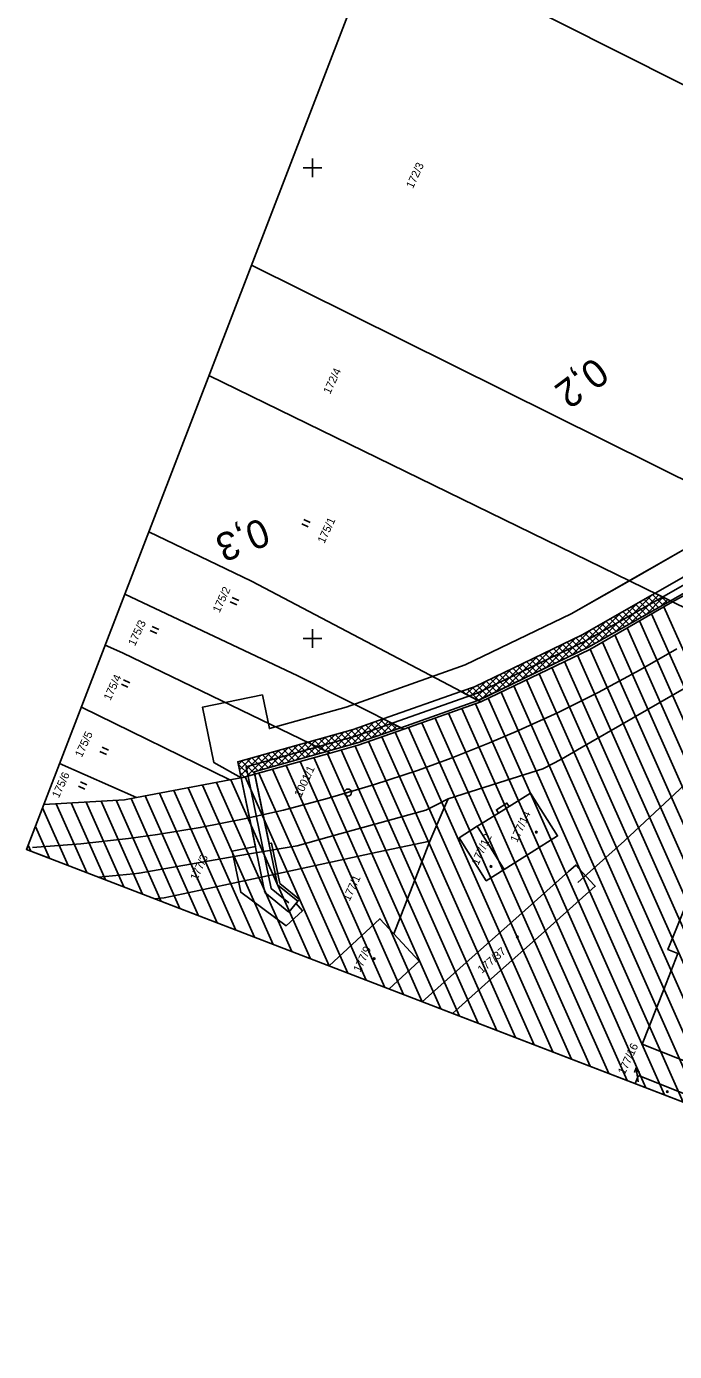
# Model space of a CAD drawing. Extents: x -755061 to -754557, y -1162352 to -1161657.
# Drawn here: x -755060.7 to -754923.1, y -1162351.5 to -1162070 of the extents above; entities that cross this region are included whole.
import ezdxf

# ---------------------------------------------------------------- set-up
doc = ezdxf.new("R2010")
doc.units = 0
for name, color, linetype in [('ADJ_Formát', 7, 'Continuous'), ('ADJ_Síť', 7, 'Continuous'), ('DTA-TZ', 7, 'Continuous'), ('DTA_DZ_DO_hranice', 7, 'Continuous'), ('DTA_DZ_DO_ostatní', 7, 'Continuous'), ('DTA_DZ_DO_ZPF', 7, 'Continuous'), ('DTA_ochranné pásmo', 7, 'Continuous'), ('DTA_projektovaný_stav', 7, 'Continuous'), ('DTA_správa_investora', 7, 'Continuous'), ('DTA_VB', 7, 'Continuous'), ('KN_Vrstva 55', 7, 'Continuous'), ('KN_Vrstva 56', 7, 'Continuous'), ('KN_Vrstva 57', 7, 'Continuous'), ('KN_Vrstva 58', 7, 'Continuous'), ('KN_Vrstva 59', 7, 'Continuous'), ('Staniceni a namezniky', 7, 'Continuous'), ('Vrstva 1', 7, 'Continuous'), ('Vrstva 53', 7, 'Continuous')]:
    doc.layers.add(name, color=color, linetype=linetype)

msp = doc.modelspace()

# ---------------------------------------------------------------- linework, layer by layer
at = {"layer": 'ADJ_Formát'}
msp.add_line((-755060.75, -1162244.84), (-755056.08, -1162246.64), dxfattribs=at)
msp.add_lwpolyline([(-754909.9, -1161852.87), (-754632.71, -1161959.54), (-754783.57, -1162351.52), (-755060.75, -1162244.84)], close=True, dxfattribs=at)
at = {"layer": 'ADJ_Síť'}
for points in [[(-755000, -1162098), (-755000, -1162100), (-755000, -1162102)], [(-754998, -1162100), (-755000, -1162100), (-755002, -1162100)], [(-754998, -1162200), (-755000, -1162200), (-755002, -1162200)], [(-754998, -1162200), (-755000, -1162200), (-755002, -1162200)], [(-755000, -1162198), (-755000, -1162200), (-755000, -1162202)], [(-755000, -1162198), (-755000, -1162200), (-755000, -1162202)]]:
    msp.add_lwpolyline(points, dxfattribs=at)
at = {"layer": 'DTA-TZ'}
msp.add_lwpolyline([(-754923.5, -1162192.2), (-754927.24, -1162190.37), (-754917.66, -1162184.92), (-754903.67, -1162174.98), (-754894.6, -1162165.92), (-754868.47, -1162140.62), (-754868.42, -1162135.23), (-754861.18, -1162138.93), (-754862.16, -1162142.69), (-754868.56, -1162149.23), (-754896.07, -1162173.88), (-754915.78, -1162187.87), (-754923.5, -1162192.2)], dxfattribs=at)
msp.add_lwpolyline([(-754984.97, -1162217.1), (-754968.47, -1162211.27), (-754964.26, -1162213.49), (-754980.63, -1162219.28)], close=True, dxfattribs=at)
at = {"layer": 'DTA_DZ_DO_hranice'}
for points in [[(-754920.36, -1162180.69), (-754945.08, -1162194.78), (-754967.54, -1162205.63), (-754992.85, -1162214.58), (-755009.16, -1162219.14), (-755010.64, -1162212), (-755023.37, -1162214.63), (-755020.94, -1162226.38), (-755020.94, -1162226.38), (-755020.94, -1162226.38), (-755015.16, -1162229.61), (-755012.14, -1162244.2), (-755017.04, -1162245.22), (-755015.23, -1162253.93), (-755005.62, -1162261.05), (-755002.11, -1162257.86), (-755003.57, -1162256.25), (-755002.73, -1162255.48), (-755006.94, -1162252.04), (-755008.71, -1162243.49), (-755009.2, -1162243.6), (-755012.26, -1162228.83)], [(-755012.26, -1162228.83), (-754996.22, -1162224.35), (-754990.29, -1162222.69), (-754980.63, -1162219.28), (-754964.26, -1162213.49), (-754941.12, -1162202.31), (-754923.5, -1162192.2), (-754915.78, -1162187.87)]]:
    msp.add_lwpolyline(points, dxfattribs=at)
at = {"layer": 'DTA_DZ_DO_ostatní'}
msp.add_lwpolyline([(-755015.16, -1162229.61), (-755012.14, -1162244.2), (-755017.04, -1162245.22), (-755015.23, -1162253.93), (-755005.62, -1162261.05), (-755002.11, -1162257.86), (-755003.57, -1162256.25), (-755002.73, -1162255.48), (-755006.94, -1162252.04), (-755008.71, -1162243.49), (-755009.2, -1162243.6), (-755012.26, -1162228.83), (-755014.83, -1162229.55)], close=True, dxfattribs=at)
at = {"layer": 'DTA_DZ_DO_ZPF'}
msp.add_lwpolyline([(-754920.36, -1162180.69), (-754932.68, -1162187.72), (-754945.08, -1162194.78), (-754967.54, -1162205.63), (-754992.85, -1162214.58), (-755009.16, -1162219.14), (-755010.64, -1162212), (-755023.37, -1162214.63), (-755020.94, -1162226.38), (-755015.16, -1162229.61), (-755014.83, -1162229.55), (-755012.26, -1162228.83), (-754996.22, -1162224.35), (-754990.29, -1162222.69), (-754980.63, -1162219.28), (-754984.97, -1162217.1), (-754968.47, -1162211.27), (-754964.26, -1162213.49), (-754941.12, -1162202.31), (-754923.5, -1162192.2), (-754927.24, -1162190.37), (-754917.66, -1162184.92)], dxfattribs=at)
at = {"layer": 'DTA_ochranné pásmo'}
for p, q in [((-754917.66, -1162184.92), (-754927.24, -1162190.37)), ((-754923.98, -1162191.97), (-754916.05, -1162187.45)), ((-754942.75, -1162199.21), (-754927.24, -1162190.37)), ((-754927.24, -1162190.37), (-754923.98, -1162191.97)), ((-754923.98, -1162191.97), (-754941.35, -1162201.87)), ((-754965.61, -1162210.25), (-754942.75, -1162199.21)), ((-754941.35, -1162201.87), (-754964.45, -1162213.03)), ((-754984.97, -1162217.1), (-754968.47, -1162211.27)), ((-754968.47, -1162211.27), (-754965.61, -1162210.25)), ((-754964.86, -1162213.17), (-754968.47, -1162211.27)), ((-754981.25, -1162218.97), (-754964.86, -1162213.17)), ((-754964.45, -1162213.03), (-754964.86, -1162213.17)), ((-755015.87, -1162226.21), (-754991.35, -1162219.35)), ((-754991.35, -1162219.35), (-754984.97, -1162217.1)), ((-754981.25, -1162218.97), (-754990.44, -1162222.21)), ((-754984.97, -1162217.1), (-754981.25, -1162218.97)), ((-754990.44, -1162222.21), (-755012.36, -1162228.34)), ((-755010.12, -1162253.96), (-755015.87, -1162226.21)), ((-755014.83, -1162229.55), (-755015.16, -1162229.61)), ((-755012.26, -1162228.83), (-755014.83, -1162229.55)), ((-755012.36, -1162228.34), (-755007.4, -1162252.32)), ((-755007.4, -1162252.32), (-755003.11, -1162255.82)), ((-755005, -1162258.15), (-755010.12, -1162253.96)), ((-755003.11, -1162255.82), (-755005, -1162258.15))]:
    msp.add_line(p, q, dxfattribs=at)
at = {"layer": 'DTA_projektovaný_stav'}
msp.add_lwpolyline([(-754758.34, -1161933.06), (-754762.34, -1161937.68), (-754763.29, -1161936.85), (-754776.47, -1161949.62), (-754777.37, -1161978.41), (-754796.3, -1162026.28), (-754809.87, -1162057.58), (-754831.07, -1162091.65), (-754857.54, -1162133.93), (-754885.68, -1162161.18), (-754896.77, -1162171.93), (-754916.86, -1162186.18), (-754942.05, -1162200.54), (-754965.03, -1162211.64), (-754990.89, -1162220.78), (-755014.11, -1162227.27), (-755008.76, -1162253.14), (-755005.05, -1162256.17)], dxfattribs=at)
at = {"layer": 'DTA_správa_investora'}
for p, q in [((-754878.81, -1162298.02), (-754925.34, -1162193.26)), ((-754881.97, -1162305.67), (-754930.57, -1162196.26)), ((-754880.39, -1162301.85), (-754927.96, -1162194.76)), ((-754885.62, -1162312.24), (-754935.81, -1162199.26)), ((-754883.56, -1162309.49), (-754933.19, -1162197.76)), ((-754893.54, -1162309.19), (-754941.04, -1162202.26)), ((-754889.58, -1162310.72), (-754938.42, -1162200.76)), ((-754901.46, -1162306.15), (-754946.44, -1162204.88)), ((-754897.5, -1162307.67), (-754943.74, -1162203.57)), ((-754909.38, -1162303.1), (-754951.85, -1162207.49)), ((-754905.42, -1162304.62), (-754949.14, -1162206.19)), ((-754917.3, -1162300.05), (-754957.25, -1162210.1)), ((-754913.34, -1162301.58), (-754954.55, -1162208.8)), ((-754929.17, -1162295.48), (-754965.41, -1162213.9)), ((-754925.22, -1162297), (-754962.66, -1162212.72)), ((-754921.26, -1162298.53), (-754959.95, -1162211.41)), ((-754941.05, -1162290.91), (-754973.92, -1162216.91)), ((-754937.09, -1162292.43), (-754971.09, -1162215.9)), ((-754933.13, -1162293.96), (-754968.25, -1162214.9)), ((-754948.97, -1162287.86), (-754979.6, -1162218.91)), ((-754945.01, -1162289.38), (-754976.76, -1162217.91)), ((-754960.85, -1162283.29), (-754988.11, -1162221.92)), ((-754956.89, -1162284.81), (-754985.27, -1162220.92)), ((-754952.93, -1162286.34), (-754982.44, -1162219.92)), ((-754976.69, -1162277.19), (-754999.73, -1162225.33)), ((-754972.73, -1162278.72), (-754996.81, -1162224.51)), ((-754968.77, -1162280.24), (-754993.89, -1162223.7)), ((-754964.81, -1162281.77), (-754990.97, -1162222.88)), ((-754988.57, -1162272.62), (-755008.49, -1162227.78)), ((-754984.61, -1162274.15), (-755005.57, -1162226.96)), ((-754980.65, -1162275.67), (-755002.65, -1162226.15)), ((-755004.41, -1162266.53), (-755020.37, -1162230.59)), ((-755000.45, -1162268.05), (-755017.34, -1162230.02)), ((-754996.49, -1162269.57), (-755014.33, -1162229.41)), ((-754992.53, -1162271.1), (-755011.41, -1162228.59)), ((-755024.2, -1162258.91), (-755035.51, -1162233.44)), ((-755020.24, -1162260.43), (-755032.49, -1162232.87)), ((-755016.28, -1162261.96), (-755029.46, -1162232.3)), ((-755012.33, -1162263.48), (-755026.43, -1162231.73)), ((-755008.37, -1162265), (-755023.4, -1162231.16)), ((-755051.92, -1162248.24), (-755057.35, -1162236.02)), ((-755047.96, -1162249.76), (-755054.46, -1162235.14)), ((-755044, -1162251.29), (-755051.26, -1162234.95)), ((-755040.04, -1162252.81), (-755048.06, -1162234.76)), ((-755036.08, -1162254.34), (-755044.86, -1162234.57)), ((-755032.12, -1162255.86), (-755041.67, -1162234.38)), ((-755028.16, -1162257.38), (-755038.54, -1162234.01)), ((-755055.88, -1162246.72), (-755058.87, -1162239.98)), ((-755059.84, -1162245.19), (-755060.4, -1162243.94))]:
    msp.add_line(p, q, dxfattribs=at)
for points in [[(-755057.07, -1162235.3), (-755060.75, -1162244.84), (-754884.82, -1162312.55), (-754851.45, -1162231.96), (-754816.22, -1162147.35), (-754802.96, -1162113.9), (-754798.15, -1162101.07), (-754793.13, -1162087.4), (-754789, -1162076.26), (-754760.29, -1162004.33), (-754756.33, -1161996.85), (-754754.27, -1161988.55), (-754747.84, -1161978.77), (-754745.89, -1161978.47), (-754750.32, -1161972.64), (-754749.74, -1161970.12), (-754747.41, -1161959.83), (-754731.42, -1161979.09), (-754717.5, -1161955.11), (-754704.12, -1161932.06), (-754747.69, -1161915.3)], [(-754915.78, -1162187.87), (-754923.5, -1162192.2), (-754941.12, -1162202.31), (-754964.26, -1162213.49), (-754980.63, -1162219.28), (-754990.29, -1162222.69), (-754996.22, -1162224.35), (-755012.26, -1162228.83), (-755014.83, -1162229.55), (-755017.58, -1162230.07), (-755037.41, -1162233.8), (-755039.91, -1162234.27), (-755057.07, -1162235.3)]]:
    msp.add_lwpolyline(points, dxfattribs=at)
at = {"layer": 'DTA_VB'}
for p, q in [((-754935.8, -1162198.7), (-754927.77, -1162190.68)), ((-754932.51, -1162196.83), (-754926.45, -1162190.76)), ((-754929.22, -1162194.96), (-754925.5, -1162191.23)), ((-754928.68, -1162191.19), (-754926.48, -1162193.39)), ((-754927.78, -1162190.68), (-754925.58, -1162192.88)), ((-754926.13, -1162190.92), (-754924.68, -1162192.37)), ((-754939.09, -1162200.58), (-754931.06, -1162192.55)), ((-754934.09, -1162194.27), (-754931.89, -1162196.47)), ((-754933.19, -1162193.76), (-754930.99, -1162195.96)), ((-754932.29, -1162193.25), (-754930.09, -1162195.45)), ((-754931.38, -1162192.73), (-754929.19, -1162194.93)), ((-754930.48, -1162192.22), (-754928.28, -1162194.42)), ((-754929.58, -1162191.71), (-754927.38, -1162193.91)), ((-754925.94, -1162193.08), (-754924.54, -1162191.69)), ((-754944.92, -1162203.58), (-754937.64, -1162196.3)), ((-754942.2, -1162202.27), (-754934.35, -1162194.42)), ((-754938.59, -1162196.84), (-754936.39, -1162199.04)), ((-754937.69, -1162196.33), (-754935.49, -1162198.53)), ((-754936.79, -1162195.81), (-754934.59, -1162198.01)), ((-754935.89, -1162195.3), (-754933.69, -1162197.5)), ((-754934.99, -1162194.79), (-754932.79, -1162196.99)), ((-754950.37, -1162206.2), (-754943.97, -1162199.8)), ((-754947.65, -1162204.89), (-754940.92, -1162198.17)), ((-754944.07, -1162199.85), (-754941.82, -1162202.09)), ((-754943.12, -1162199.39), (-754940.9, -1162201.61)), ((-754942.19, -1162198.89), (-754940, -1162201.09)), ((-754941.29, -1162198.38), (-754939.09, -1162200.58)), ((-754940.39, -1162197.87), (-754938.19, -1162200.07)), ((-754939.49, -1162197.35), (-754937.29, -1162199.55)), ((-754955.82, -1162208.83), (-754949.44, -1162202.44)), ((-754953.1, -1162207.52), (-754946.7, -1162201.12)), ((-754949.79, -1162202.61), (-754947.55, -1162204.85)), ((-754948.84, -1162202.15), (-754946.6, -1162204.39)), ((-754947.88, -1162201.69), (-754945.64, -1162203.93)), ((-754946.93, -1162201.23), (-754944.69, -1162203.47)), ((-754945.98, -1162200.77), (-754943.73, -1162203.01)), ((-754945.02, -1162200.31), (-754942.78, -1162202.55)), ((-754961.27, -1162211.45), (-754954.91, -1162205.09)), ((-754958.55, -1162210.14), (-754952.17, -1162203.76)), ((-754955.51, -1162205.38), (-754953.28, -1162207.6)), ((-754954.56, -1162204.92), (-754952.33, -1162207.15)), ((-754953.6, -1162204.45), (-754951.37, -1162206.69)), ((-754952.65, -1162203.99), (-754950.42, -1162206.23)), ((-754951.7, -1162203.53), (-754949.46, -1162205.77)), ((-754950.74, -1162203.07), (-754948.51, -1162205.31)), ((-754965.49, -1162212.84), (-754960.38, -1162207.73)), ((-754963.99, -1162212.76), (-754957.65, -1162206.41)), ((-754961.23, -1162208.14), (-754959.01, -1162210.36)), ((-754960.28, -1162207.68), (-754958.06, -1162209.9)), ((-754959.33, -1162207.22), (-754957.1, -1162209.44)), ((-754958.37, -1162206.76), (-754956.15, -1162208.98)), ((-754957.42, -1162206.3), (-754955.19, -1162208.52)), ((-754956.47, -1162205.84), (-754954.24, -1162208.06)), ((-754968.27, -1162211.37), (-754967.99, -1162211.1)), ((-754968.13, -1162211.14), (-754967.49, -1162211.79)), ((-754967.34, -1162211.86), (-754965.81, -1162210.32)), ((-754967.08, -1162210.78), (-754964.74, -1162213.12)), ((-754966.42, -1162212.35), (-754963.12, -1162209.05)), ((-754966.04, -1162210.41), (-754963.79, -1162212.66)), ((-754965.05, -1162209.98), (-754962.83, -1162212.2)), ((-754964.09, -1162209.52), (-754961.88, -1162211.74)), ((-754963.14, -1162209.06), (-754960.92, -1162211.28)), ((-754962.19, -1162208.6), (-754959.97, -1162210.82)), ((-754995.67, -1162223.67), (-754991.34, -1162219.35)), ((-754993.7, -1162223.13), (-754989.16, -1162218.58)), ((-754991.86, -1162219.5), (-754989.49, -1162221.88)), ((-754991.74, -1162222.58), (-754986.97, -1162217.8)), ((-754990.79, -1162219.16), (-754988.44, -1162221.51)), ((-754989.75, -1162218.79), (-754987.4, -1162221.14)), ((-754989.7, -1162221.95), (-754984.89, -1162217.14)), ((-754988.7, -1162218.42), (-754986.35, -1162220.77)), ((-754987.66, -1162218.05), (-754985.31, -1162220.4)), ((-754987.52, -1162221.18), (-754983.95, -1162217.61)), ((-754986.61, -1162217.68), (-754984.26, -1162220.03)), ((-754985.57, -1162217.31), (-754983.22, -1162219.66)), ((-754985.33, -1162220.41), (-754983.01, -1162218.08)), ((-754983.76, -1162217.7), (-754982.17, -1162219.29)), ((-754983.14, -1162219.63), (-754982.07, -1162218.56)), ((-755005.48, -1162226.42), (-755001.16, -1162222.09)), ((-755003.52, -1162225.87), (-754999.2, -1162221.55)), ((-755001.81, -1162222.28), (-754999.38, -1162224.71)), ((-755001.56, -1162225.32), (-754997.23, -1162221)), ((-755000.71, -1162221.97), (-754998.27, -1162224.4)), ((-754999.6, -1162221.66), (-754997.17, -1162224.09)), ((-754999.59, -1162224.77), (-754995.27, -1162220.45)), ((-754998.5, -1162221.35), (-754996.06, -1162223.78)), ((-754997.63, -1162224.22), (-754993.31, -1162219.9)), ((-754997.39, -1162221.04), (-754994.96, -1162223.48)), ((-754996.29, -1162220.73), (-754993.85, -1162223.17)), ((-754995.18, -1162220.42), (-754992.75, -1162222.86)), ((-754994.08, -1162220.11), (-754991.64, -1162222.55)), ((-754992.97, -1162219.81), (-754990.54, -1162222.24)), ((-755015.26, -1162229.13), (-755010.97, -1162224.84)), ((-755014.05, -1162229.33), (-755009.01, -1162224.29)), ((-755012.86, -1162225.37), (-755010.43, -1162227.8)), ((-755011.76, -1162225.06), (-755009.32, -1162227.49)), ((-755011.37, -1162228.06), (-755007.05, -1162223.74)), ((-755010.65, -1162224.75), (-755008.22, -1162227.18)), ((-755009.55, -1162224.44), (-755007.11, -1162226.87)), ((-755009.41, -1162227.52), (-755005.08, -1162223.19)), ((-755008.44, -1162224.13), (-755006.01, -1162226.57)), ((-755007.45, -1162226.97), (-755003.12, -1162222.64)), ((-755007.34, -1162223.82), (-755004.9, -1162226.26)), ((-755006.23, -1162223.51), (-755003.8, -1162225.95)), ((-755005.13, -1162223.2), (-755002.69, -1162225.64)), ((-755004.02, -1162222.89), (-755001.59, -1162225.33)), ((-755002.92, -1162222.59), (-755000.48, -1162225.02)), ((-755015.76, -1162226.71), (-755013.34, -1162229.13)), ((-755015.75, -1162226.78), (-755014.9, -1162225.94)), ((-755015.5, -1162227.95), (-755012.94, -1162225.39)), ((-755015.07, -1162225.98), (-755012.27, -1162228.79)), ((-755013.97, -1162225.68), (-755011.54, -1162228.11)), ((-755015.39, -1162228.5), (-755014.45, -1162229.44))]:
    msp.add_line(p, q, dxfattribs=at)
for points in [[(-754927.24, -1162190.37), (-754942.75, -1162199.21), (-754965.61, -1162210.25), (-754968.47, -1162211.27), (-754964.86, -1162213.17), (-754941.35, -1162201.87), (-754923.98, -1162191.97)], [(-754984.97, -1162217.1), (-754981.25, -1162218.97), (-754990.44, -1162222.21), (-755012.36, -1162228.34), (-755012.26, -1162228.83), (-755014.83, -1162229.55), (-755015.16, -1162229.61), (-755015.87, -1162226.21), (-754991.35, -1162219.35)]]:
    msp.add_lwpolyline(points, close=True, dxfattribs=at)
at = {"layer": 'KN_Vrstva 55'}
for p, q in [((-755012.97, -1162120.69), (-754900.06, -1162176.77)), ((-755021.99, -1162144.14), (-754923.5, -1162192.2)), ((-754905.78, -1162201), (-754923.5, -1162192.2)), ((-754980.63, -1162219.28), (-754964.26, -1162213.49)), ((-755037.41, -1162233.8), (-755017.58, -1162230.07)), ((-754959.28, -1162249.1), (-754965.02, -1162239.9))]:
    msp.add_line(p, q, dxfattribs=at)
for points in [[(-754858.37, -1162113.93), (-754985.69, -1162049.81)], [(-755034.76, -1162177.32), (-755012.93, -1162187.79), (-754964.26, -1162213.49)], [(-754923.5, -1162192.2), (-754915.78, -1162187.87), (-754900.06, -1162176.77)], [(-755039.87, -1162190.6), (-755003.14, -1162207.94), (-754980.63, -1162219.28)], [(-754923.5, -1162192.2), (-754941.12, -1162202.31), (-754964.26, -1162213.49)], [(-755044.04, -1162201.44), (-755040.35, -1162203.08), (-754996.22, -1162224.35)], [(-754971.15, -1162234.1), (-754958.95, -1162230.19), (-754951.07, -1162227.67), (-754947.14, -1162225.65), (-754943.74, -1162223.69), (-754908.27, -1162203.24), (-754905.78, -1162201)], [(-755049.1, -1162214.57), (-755017.58, -1162230.07)], [(-754996.22, -1162224.35), (-754990.29, -1162222.69), (-754980.63, -1162219.28)], [(-755017.58, -1162230.07), (-755014.83, -1162229.55), (-754996.22, -1162224.35)], [(-755053.71, -1162226.55), (-755037.41, -1162233.8)], [(-755057.07, -1162235.3), (-755039.91, -1162234.27), (-755037.41, -1162233.8)], [(-754965.02, -1162239.9), (-754964.51, -1162239.63), (-754960.48, -1162237.12), (-754960.95, -1162236.39), (-754958.69, -1162234.97), (-754958.23, -1162235.71), (-754953.68, -1162232.85), (-754947.93, -1162241.97), (-754953.52, -1162245.48), (-754959.28, -1162249.1)], [(-755045.47, -1162250.72), (-755038.01, -1162250.05), (-755036.82, -1162249.84), (-755013.79, -1162245.86), (-755003.23, -1162244.03), (-754994.22, -1162241.55), (-754975.93, -1162236.51), (-754973.51, -1162235.29), (-754971.15, -1162234.1)], [(-754971.15, -1162234.1), (-754972, -1162236.02), (-754975.1, -1162243.04)], [(-754959.28, -1162249.1), (-754963.09, -1162251.49), (-754968.85, -1162242.38), (-754965.02, -1162239.9)], [(-754975.1, -1162243.04), (-754986.3, -1162245.44), (-755006.22, -1162249.72), (-755027.5, -1162254.28), (-755031.53, -1162255.15), (-755033.53, -1162255.32)], [(-754982.72, -1162262.75), (-754982.38, -1162261.87), (-754977.59, -1162249.49), (-754975.1, -1162243.04)], [(-754956.8, -1162259.49), (-754945.64, -1162249.55), (-754944.05, -1162248.14), (-754940.25, -1162252.33), (-754939.94, -1162252.67), (-754950.82, -1162262.37), (-754961.31, -1162271.72), (-754970.23, -1162279.68)], [(-754922.63, -1162261.43), (-754921.01, -1162257.39), (-754914.72, -1162259.89), (-754913.29, -1162256.54), (-754910.69, -1162257.6), (-754913.05, -1162263.33), (-754904.47, -1162266.73), (-754905.81, -1162270.11), (-754910.45, -1162281.8), (-754914.62, -1162292.29), (-754930, -1162286.19), (-754925.41, -1162274.6), (-754922.38, -1162266.96), (-754924.5, -1162266.11), (-754922.63, -1162261.43)], [(-754996.49, -1162269.58), (-754985.67, -1162259.55), (-754982.72, -1162262.75)], [(-754976.68, -1162277.2), (-754967.36, -1162268.89), (-754956.8, -1162259.49)], [(-754982.72, -1162262.75), (-754977.34, -1162268.59), (-754983.75, -1162274.48)], [(-754931.45, -1162294.6), (-754930.78, -1162292.9)], [(-754930.78, -1162292.9), (-754917.8, -1162298.01), (-754918.43, -1162299.61)]]:
    msp.add_lwpolyline(points, dxfattribs=at)
at = {"layer": 'KN_Vrstva 56'}
msp.add_line((-754958.23, -1162235.71), (-754960.48, -1162237.12), dxfattribs=at)
at = {"layer": 'KN_Vrstva 57'}
for p, q in [((-754931.24, -1162291.21), (-754931.61, -1162292.26)), ((-754930.85, -1162294.18), (-754931.24, -1162291.21)), ((-754931.24, -1162291.21), (-754930.61, -1162292.13))]:
    msp.add_line(p, q, dxfattribs=at)
at = {"layer": 'KN_Vrstva 58'}
for p, q in [((-755000.92, -1162176.26), (-755002.28, -1162175.63)), ((-755000.5, -1162175.35), (-755001.86, -1162174.72)), ((-755015.67, -1162191.96), (-755017.03, -1162191.32)), ((-755016.1, -1162192.86), (-755017.46, -1162192.23)), ((-755033.1, -1162198.97), (-755034.46, -1162198.34)), ((-755032.67, -1162198.07), (-755034.03, -1162197.43)), ((-755039.22, -1162210.35), (-755040.58, -1162209.72)), ((-755038.79, -1162209.45), (-755040.15, -1162208.81)), ((-755043.78, -1162224.63), (-755045.14, -1162224)), ((-755043.35, -1162223.73), (-755044.71, -1162223.09)), ((-755047.93, -1162231.09), (-755049.28, -1162230.46)), ((-755048.35, -1162232), (-755049.71, -1162231.37))]:
    msp.add_line(p, q, dxfattribs=at)
at = {"layer": 'KN_Vrstva 59'}
for centre in [(-754952.44, -1162241.15), (-754962.08, -1162248.45), (-754956.47, -1162263.43), (-754986.89, -1162268.03), (-754924.62, -1162296.3)]:
    msp.add_circle(centre, 0.175, dxfattribs=at)
at = {"layer": 'Staniceni a namezniky'}
msp.add_circle((-754992.48, -1162232.74), 0.75, dxfattribs=at)
at = {"layer": 'Vrstva 1'}
for points in [[(-754922.58, -1162202.18), (-754930.39, -1162206.7), (-754939.31, -1162211.5), (-754947.84, -1162215.73), (-754956.28, -1162219.59), (-754962.4, -1162222.2), (-754970.58, -1162225.44), (-754977.51, -1162227.97), (-754987.04, -1162231.13), (-754996.89, -1162234.04), (-755006.19, -1162236.46), (-755014.55, -1162238.36), (-755023.83, -1162240.18), (-755032.89, -1162241.66), (-755039.07, -1162242.52), (-755049.19, -1162243.63), (-755059.44, -1162244.4)], [(-754904.65, -1162212.5), (-754911.48, -1162220.81), (-754920.93, -1162231.04), (-754933.71, -1162243.01), (-754943.62, -1162251.86)]]:
    msp.add_lwpolyline(points, dxfattribs=at)
at = {"layer": 'Vrstva 53'}
msp.add_lwpolyline([(-754915.78, -1162187.87), (-754923.5, -1162192.2), (-754941.12, -1162202.31), (-754964.26, -1162213.49), (-754980.63, -1162219.28), (-754990.29, -1162222.69), (-754996.22, -1162224.35), (-755014.83, -1162229.55), (-755017.58, -1162230.07), (-755037.41, -1162233.8), (-755039.91, -1162234.27), (-755057.07, -1162235.3)], dxfattribs=at)

# ---------------------------------------------------------------- texts
at = {"layer": 'KN_Vrstva 57'}
for s, rotation, p in [('172/3', 65, (-754978.68, -1162104.52)), ('172/4', 65, (-754996.26, -1162148.21)), ('175/1', 65, (-754997.49, -1162179.94)), ('175/2', 65, (-755019.76, -1162194.66)), ('175/3', 65, (-755037.72, -1162201.74)), ('175/4', 65, (-755042.93, -1162213.32)), ('175/5', 65, (-755049.02, -1162225.4)), ('1001/1', 65, (-755002.41, -1162233.85)), ('175/6', 65, (-755053.91, -1162234.04)), ('177/14', 65, (-754956.55, -1162243.48)), ('177/12', 65, (-754964.8, -1162248.3)), ('177/3', 65, (-755024.54, -1162251.56)), ('177/1', 65, (-754992.13, -1162255.96)), ('177/9', 65, (-754989.88, -1162271.07)), ('177/37', 40.664, (-754964.03, -1162271.28)), ('177/16', 65, (-754933.7, -1162292.82))]:
    msp.add_text(s, height=1.7, rotation=rotation, dxfattribs=at).set_placement(p)
at = {"layer": 'Staniceni a namezniky'}
for s, rotation, p in [('0,2', 216.7166, (-754940.07, -1162139.99)), ('0,3', 201.4151, (-755010.69, -1162174.24))]:
    msp.add_text(s, height=6, rotation=rotation, dxfattribs=at).set_placement(p)

doc.saveas('drawing.dxf')
